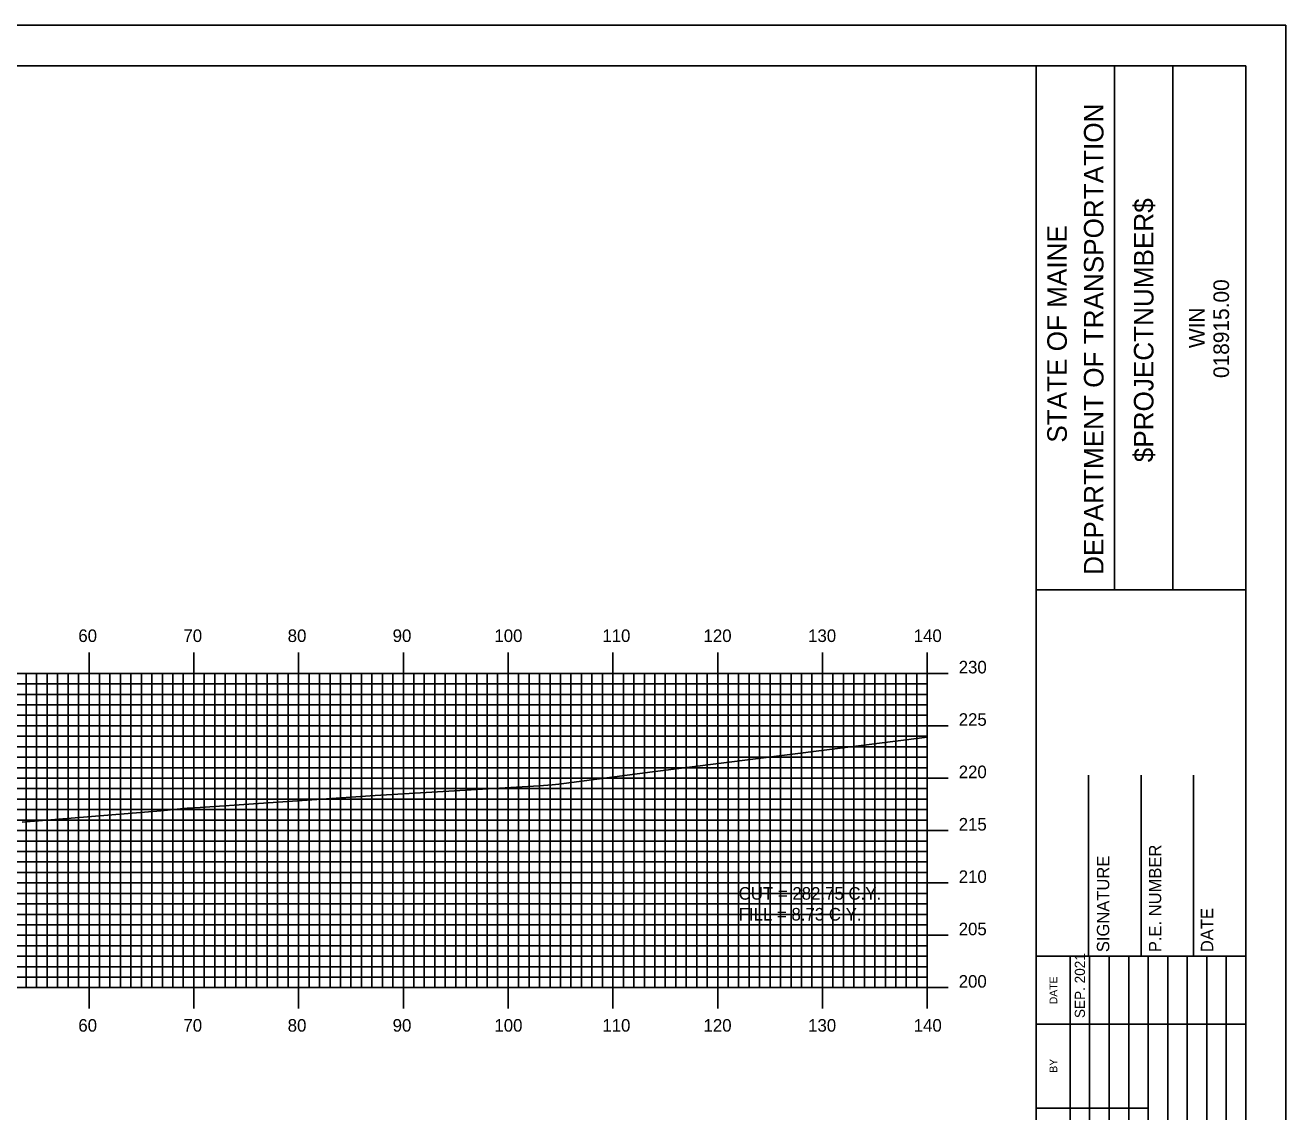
# Model space of a CAD drawing. Extents: x 851742 to 852085, y 364785 to 365005.
# Drawn here: x 851961.6 to 852081.9, y 364901.4 to 365005.1 of the extents above; entities that cross this region are included whole.
import ezdxf

# ---------------------------------------------------------------- set-up
doc = ezdxf.new("R2010")
doc.units = 0
for name, color, linetype in [('BORDER', 7, 'Continuous'), ('D_Text_Standard', 7, 'Continuous'), ('H_V ANNOTATION', 7, 'Continuous'), ('MAJOR', 7, 'Continuous'), ('MINOR', 7, 'Continuous'), ('PLOT BOUNDARY', 7, 'Continuous'), ('S_Roadway_Centerline', 7, 'Continuous')]:
    doc.layers.add(name, color=color, linetype=linetype)

msp = doc.modelspace()

# ---------------------------------------------------------------- linework, layer by layer
at = {"layer": 'BORDER'}
for p, q in [((852058.1, 364791.23), (852058.1, 365001.23)), ((852065.56, 364951.23), (852065.56, 365001.23)), ((852071.15, 364951.23), (852071.15, 365001.23)), ((852058.11, 364951.22), (852078.1, 364951.22)), ((852063.1, 364916.24), (852063.1, 364933.53)), ((852068.1, 364916.24), (852068.1, 364933.53)), ((852073.1, 364916.24), (852073.1, 364933.53)), ((852058.1, 364916.24), (852078.1, 364916.24))]:
    msp.add_line(p, q, dxfattribs=at)
msp.add_lwpolyline([(851758.1, 364791.23), (852078.1, 364791.23), (852078.1, 365001.23), (851758.1, 365001.23)], close=True, dxfattribs=at)
for points in [[(852061.33, 364909.74), (852061.33, 364916.24)], [(852063.2, 364881.24), (852063.2, 364916.24)], [(852065.06, 364916.24), (852065.06, 364881.24)], [(852066.93, 364881.24), (852066.93, 364916.24)], [(852068.79, 364881.24), (852068.79, 364916.24)], [(852070.65, 364881.24), (852070.65, 364916.24)], [(852072.52, 364881.24), (852072.52, 364916.24)], [(852074.38, 364881.24), (852074.38, 364916.24)], [(852076.24, 364881.24), (852076.24, 364916.24)], [(852061.34, 364881.24), (852061.34, 364914.83)], [(852058.1, 364909.74), (852078.1, 364909.74)], [(852058.1, 364901.74), (852061.34, 364901.74)], [(852061.33, 364901.74), (852068.79, 364901.74)]]:
    msp.add_lwpolyline(points, dxfattribs=at)
at = {"layer": 'MAJOR'}
for p, q in [((851967.7, 364945.24), (851967.7, 364943.23)), ((851977.7, 364945.24), (851977.7, 364943.23)), ((851987.7, 364945.24), (851987.7, 364943.23)), ((851997.7, 364945.24), (851997.7, 364943.23)), ((852007.7, 364945.24), (852007.7, 364943.23)), ((852017.7, 364945.24), (852017.7, 364943.23)), ((852027.7, 364945.24), (852027.7, 364943.23)), ((852037.7, 364945.24), (852037.7, 364943.23)), ((852047.7, 364945.24), (852047.7, 364943.23)), ((851767.7, 364943.23), (852047.7, 364943.23)), ((851767.7, 364943.23), (852047.7, 364943.23)), ((851967.7, 364913.23), (851967.7, 364943.23)), ((851977.7, 364913.23), (851977.7, 364943.23)), ((851987.7, 364913.23), (851987.7, 364943.23)), ((851997.7, 364913.23), (851997.7, 364943.23)), ((852007.7, 364913.23), (852007.7, 364943.23)), ((852017.7, 364913.23), (852017.7, 364943.23)), ((852027.7, 364913.23), (852027.7, 364943.23)), ((852037.7, 364913.23), (852037.7, 364943.23)), ((852049.71, 364943.23), (852045.7, 364943.23)), ((852047.7, 364913.23), (852047.7, 364943.23)), ((852047.7, 364913.23), (852047.7, 364943.23)), ((851767.7, 364938.23), (852047.7, 364938.23)), ((852049.71, 364938.23), (852045.7, 364938.23)), ((851767.7, 364933.23), (852047.7, 364933.23)), ((852049.71, 364933.23), (852045.7, 364933.23)), ((851767.7, 364928.23), (852047.7, 364928.23)), ((852049.71, 364928.23), (852045.7, 364928.23)), ((851767.7, 364923.23), (852047.7, 364923.23)), ((852049.71, 364923.23), (852045.7, 364923.23)), ((851767.7, 364918.23), (852047.7, 364918.23)), ((852049.71, 364918.23), (852045.7, 364918.23)), ((851767.7, 364913.23), (852047.7, 364913.23)), ((851767.7, 364913.23), (852047.7, 364913.23)), ((851967.7, 364911.23), (851967.7, 364913.23)), ((851977.7, 364911.23), (851977.7, 364913.23)), ((851987.7, 364911.23), (851987.7, 364913.23)), ((851997.7, 364911.23), (851997.7, 364913.23)), ((852007.7, 364911.23), (852007.7, 364913.23)), ((852017.7, 364911.23), (852017.7, 364913.23)), ((852027.7, 364911.23), (852027.7, 364913.23)), ((852037.7, 364911.23), (852037.7, 364913.23)), ((852049.71, 364913.23), (852045.7, 364913.23)), ((852047.7, 364911.23), (852047.7, 364913.23))]:
    msp.add_line(p, q, dxfattribs=at)
at = {"layer": 'MINOR'}
for p, q in [((851961.7, 364913.23), (851961.7, 364943.23)), ((851962.7, 364913.23), (851962.7, 364943.23)), ((851963.7, 364913.23), (851963.7, 364943.23)), ((851964.7, 364913.23), (851964.7, 364943.23)), ((851965.7, 364913.23), (851965.7, 364943.23)), ((851966.7, 364913.23), (851966.7, 364943.23)), ((851968.7, 364913.23), (851968.7, 364943.23)), ((851969.7, 364913.23), (851969.7, 364943.23)), ((851970.7, 364913.23), (851970.7, 364943.23)), ((851971.7, 364913.23), (851971.7, 364943.23)), ((851972.7, 364913.23), (851972.7, 364943.23)), ((851973.7, 364913.23), (851973.7, 364943.23)), ((851974.7, 364913.23), (851974.7, 364943.23)), ((851975.7, 364913.23), (851975.7, 364943.23)), ((851976.7, 364913.23), (851976.7, 364943.23)), ((851978.7, 364913.23), (851978.7, 364943.23)), ((851979.7, 364913.23), (851979.7, 364943.23)), ((851980.7, 364913.23), (851980.7, 364943.23)), ((851981.7, 364913.23), (851981.7, 364943.23)), ((851982.7, 364913.23), (851982.7, 364943.23)), ((851983.7, 364913.23), (851983.7, 364943.23)), ((851984.7, 364913.23), (851984.7, 364943.23)), ((851985.7, 364913.23), (851985.7, 364943.23)), ((851986.7, 364913.23), (851986.7, 364943.23)), ((851988.7, 364913.23), (851988.7, 364943.23)), ((851989.7, 364913.23), (851989.7, 364943.23)), ((851990.7, 364913.23), (851990.7, 364943.23)), ((851991.7, 364913.23), (851991.7, 364943.23)), ((851992.7, 364913.23), (851992.7, 364943.23)), ((851993.7, 364913.23), (851993.7, 364943.23)), ((851994.7, 364913.23), (851994.7, 364943.23)), ((851995.7, 364913.23), (851995.7, 364943.23)), ((851996.7, 364913.23), (851996.7, 364943.23)), ((851998.7, 364913.23), (851998.7, 364943.23)), ((851999.7, 364913.23), (851999.7, 364943.23)), ((852000.7, 364913.23), (852000.7, 364943.23)), ((852001.7, 364913.23), (852001.7, 364943.23)), ((852002.7, 364913.23), (852002.7, 364943.23)), ((852003.7, 364913.23), (852003.7, 364943.23)), ((852004.7, 364913.23), (852004.7, 364943.23)), ((852005.7, 364913.23), (852005.7, 364943.23)), ((852006.7, 364913.23), (852006.7, 364943.23)), ((852008.7, 364913.23), (852008.7, 364943.23)), ((852009.7, 364913.23), (852009.7, 364943.23)), ((852010.7, 364913.23), (852010.7, 364943.23)), ((852011.7, 364913.23), (852011.7, 364943.23)), ((852012.7, 364913.23), (852012.7, 364943.23)), ((852013.7, 364913.23), (852013.7, 364943.23)), ((852014.7, 364913.23), (852014.7, 364943.23)), ((852015.7, 364913.23), (852015.7, 364943.23)), ((852016.7, 364913.23), (852016.7, 364943.23)), ((852018.7, 364913.23), (852018.7, 364943.23)), ((852019.7, 364913.23), (852019.7, 364943.23)), ((852020.7, 364913.23), (852020.7, 364943.23)), ((852021.7, 364913.23), (852021.7, 364943.23)), ((852022.7, 364913.23), (852022.7, 364943.23)), ((852023.7, 364913.23), (852023.7, 364943.23)), ((852024.7, 364913.23), (852024.7, 364943.23)), ((852025.7, 364913.23), (852025.7, 364943.23)), ((852026.7, 364913.23), (852026.7, 364943.23)), ((852028.7, 364913.23), (852028.7, 364943.23)), ((852029.7, 364913.23), (852029.7, 364943.23)), ((852030.7, 364913.23), (852030.7, 364943.23)), ((852031.7, 364913.23), (852031.7, 364943.23)), ((852032.7, 364913.23), (852032.7, 364943.23)), ((852033.7, 364913.23), (852033.7, 364943.23)), ((852034.7, 364913.23), (852034.7, 364943.23)), ((852035.7, 364913.23), (852035.7, 364943.23)), ((852036.7, 364913.23), (852036.7, 364943.23)), ((852038.7, 364913.23), (852038.7, 364943.23)), ((852039.7, 364913.23), (852039.7, 364943.23)), ((852040.7, 364913.23), (852040.7, 364943.23)), ((852041.7, 364913.23), (852041.7, 364943.23)), ((852042.7, 364913.23), (852042.7, 364943.23)), ((852043.7, 364913.23), (852043.7, 364943.23)), ((852044.7, 364913.23), (852044.7, 364943.23)), ((852045.7, 364913.23), (852045.7, 364943.23)), ((852046.7, 364913.23), (852046.7, 364943.23)), ((851767.7, 364942.23), (852047.7, 364942.23)), ((852047.7, 364942.23), (852045.7, 364942.23)), ((851767.7, 364941.23), (852047.7, 364941.23)), ((852047.7, 364941.23), (852045.7, 364941.23)), ((851767.7, 364940.23), (852047.7, 364940.23)), ((852047.7, 364940.23), (852045.7, 364940.23)), ((851767.7, 364939.23), (852047.7, 364939.23)), ((852047.7, 364939.23), (852045.7, 364939.23)), ((851767.7, 364937.23), (852047.7, 364937.23)), ((852047.7, 364937.23), (852045.7, 364937.23)), ((851767.7, 364936.23), (852047.7, 364936.23)), ((852047.7, 364936.23), (852045.7, 364936.23)), ((851767.7, 364935.23), (852047.7, 364935.23)), ((852047.7, 364935.23), (852045.7, 364935.23)), ((851767.7, 364934.23), (852047.7, 364934.23)), ((852047.7, 364934.23), (852045.7, 364934.23)), ((851767.7, 364932.23), (852047.7, 364932.23)), ((852047.7, 364932.23), (852045.7, 364932.23)), ((851767.7, 364931.23), (852047.7, 364931.23)), ((852047.7, 364931.23), (852045.7, 364931.23)), ((851767.7, 364930.23), (852047.7, 364930.23)), ((852047.7, 364930.23), (852045.7, 364930.23)), ((851767.7, 364929.23), (852047.7, 364929.23)), ((852047.7, 364929.23), (852045.7, 364929.23)), ((851767.7, 364927.23), (852047.7, 364927.23)), ((851767.7, 364926.23), (852047.7, 364926.23)), ((852047.7, 364927.23), (852045.7, 364927.23)), ((852047.7, 364926.23), (852045.7, 364926.23)), ((851767.7, 364925.23), (852047.7, 364925.23)), ((852047.7, 364925.23), (852045.7, 364925.23)), ((851767.7, 364924.23), (852047.7, 364924.23)), ((852047.7, 364924.23), (852045.7, 364924.23)), ((851767.7, 364922.23), (852047.7, 364922.23)), ((852047.7, 364922.23), (852045.7, 364922.23)), ((851767.7, 364921.23), (852047.7, 364921.23)), ((851767.7, 364920.23), (852047.7, 364920.23)), ((852047.7, 364921.23), (852045.7, 364921.23)), ((852047.7, 364920.23), (852045.7, 364920.23)), ((851767.7, 364919.23), (852047.7, 364919.23)), ((852047.7, 364919.23), (852045.7, 364919.23)), ((851767.7, 364917.23), (852047.7, 364917.23)), ((852047.7, 364917.23), (852045.7, 364917.23)), ((851767.7, 364916.23), (852047.7, 364916.23)), ((852047.7, 364916.23), (852045.7, 364916.23)), ((851767.7, 364915.23), (852047.7, 364915.23)), ((851767.7, 364914.23), (852047.7, 364914.23)), ((852047.7, 364915.23), (852045.7, 364915.23)), ((852047.7, 364914.23), (852045.7, 364914.23))]:
    msp.add_line(p, q, dxfattribs=at)
at = {"layer": 'PLOT BOUNDARY'}
msp.add_lwpolyline([(851741.92, 364785.11), (852081.92, 364785.11), (852081.92, 365005.11), (851741.92, 365005.11)], close=True, dxfattribs=at)
at = {"layer": 'S_Roadway_Centerline'}
msp.add_lwpolyline([(851961.31, 364929.04), (851974.57, 364930.11), (851976.42, 364930.31), (851977.08, 364930.36), (851978.31, 364930.44), (851995.01, 364931.58), (852010.65, 364932.51), (852011.91, 364932.6), (852012.54, 364932.67), (852021.48, 364933.82), (852047.7, 364937.14)], dxfattribs=at)

# ---------------------------------------------------------------- texts
at = {"layer": 'BORDER'}
for s, height, p in [('DEPARTMENT OF TRANSPORTATION', 1.8635, (852064.52, 364952.64)), ('$PROJECTNUMBER$', 1.8635, (852069.29, 364963.39)), ('STATE OF MAINE', 1.8635, (852061.02, 364965.26)), ('018915.00', 1.491, (852076.5, 364971.43)), ('WIN', 1.491, (852074.18, 364974.29)), ('P.E. NUMBER', 1.1811, (852070.03, 364916.62)), ('SIGNATURE', 1.181, (852065.07, 364916.62)), ('DATE', 1.181, (852074.99, 364916.62)), ('SEP. 2021', 0.969, (852062.75, 364910.33)), ('DATE', 0.743, (852060.11, 364911.65)), ('BY', 0.743, (852060.11, 364905.11))]:
    msp.add_text(s, height=height, rotation=90, dxfattribs=at).set_placement(p)
at = {"layer": 'D_Text_Standard'}
for s, p in [('CUT = 282.75 C.Y.', (852029.7, 364921.63)), ('FILL = 8.73 C.Y.', (852029.7, 364919.64))]:
    msp.add_text(s, height=1.2, dxfattribs=at).set_placement(p)
at = {"layer": 'H_V ANNOTATION'}
for s, p in [('60', (851966.68, 364946.23)), ('70', (851976.71, 364946.23)), ('80', (851986.66, 364946.23)), ('90', (851996.68, 364946.23)), ('100', (852006.39, 364946.23)), ('110', (852016.69, 364946.23)), ('120', (852026.35, 364946.23)), ('130', (852036.33, 364946.23)), ('140', (852046.41, 364946.23)), ('230', (852050.7, 364943.23)), ('225', (852050.7, 364938.23)), ('220', (852050.7, 364933.23)), ('215', (852050.7, 364928.23)), ('210', (852050.7, 364923.23)), ('205', (852050.7, 364918.23)), ('200', (852050.7, 364913.23)), ('60', (851966.68, 364909.03)), ('70', (851976.71, 364909.03)), ('80', (851986.66, 364909.03)), ('90', (851996.68, 364909.03)), ('100', (852006.39, 364909.03)), ('110', (852016.69, 364909.03)), ('120', (852026.35, 364909.03)), ('130', (852036.33, 364909.03)), ('140', (852046.41, 364909.03))]:
    msp.add_text(s, height=1.2, dxfattribs=at).set_placement(p)

doc.saveas('drawing.dxf')
